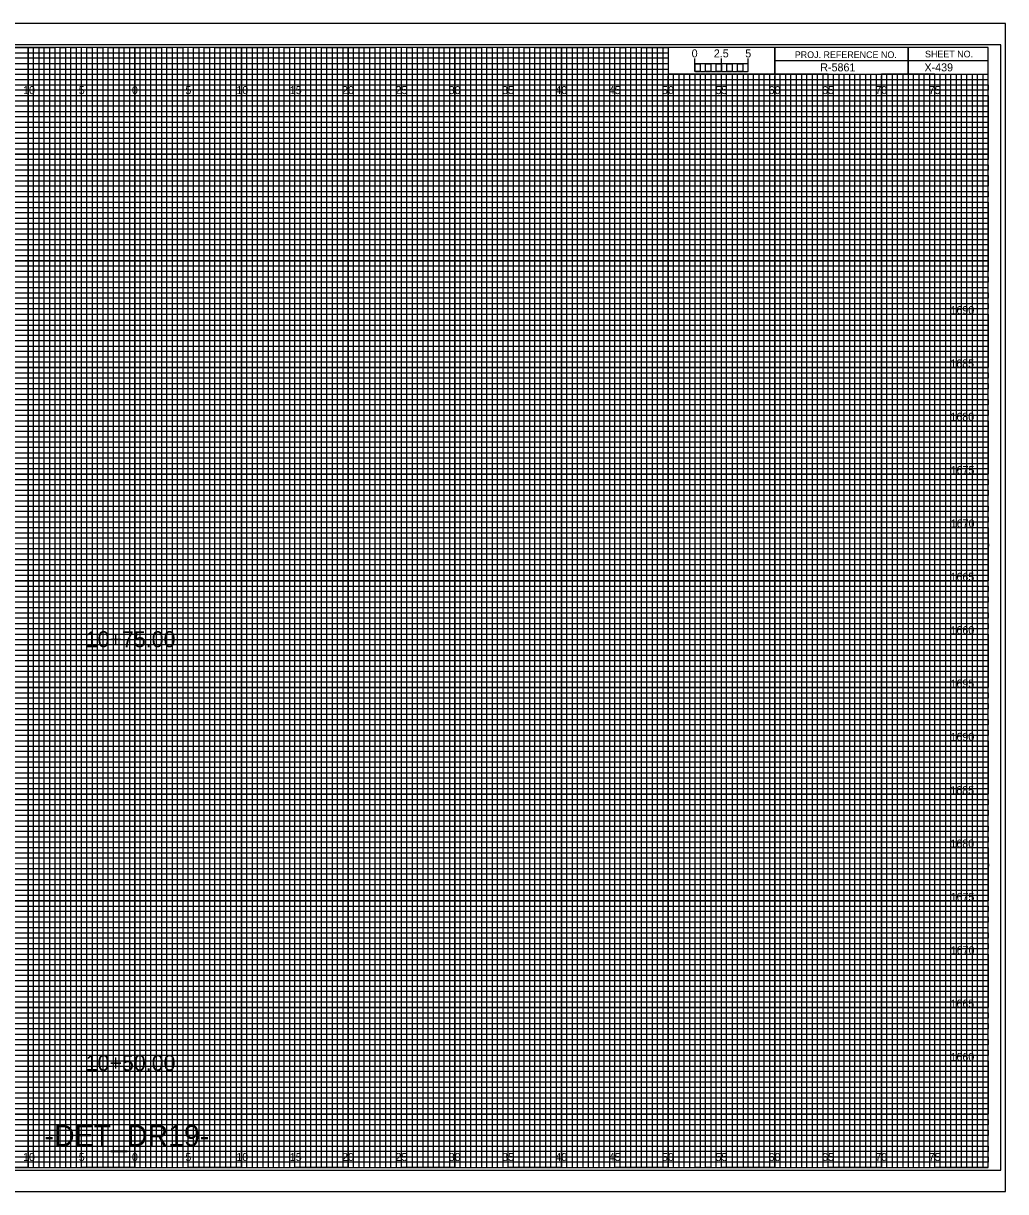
# Model space of a CAD drawing. Extents: x -7 to 162, y -2 to 327.
# Drawn here: x 69.5 to 161.7, y 107.7 to 217.2 of the extents above; entities that cross this region are included whole.
import ezdxf

# ---------------------------------------------------------------- set-up
doc = ezdxf.new("R2010")
doc.units = 0
for name, color, linetype in [('Prop Horizontal Alignment', 7, 'Continuous'), ('Prop XS Alignment Label', 7, 'Continuous'), ('Prop XS Bar Scale Labels', 7, 'Continuous'), ('Prop XS Project Number', 7, 'Continuous'), ('Prop XS Sheet Number', 7, 'Continuous'), ('Raster_Level_0', 7, 'Continuous'), ('Scratch_Level_3', 7, 'Continuous'), ('Sheet Cross Section CELL', 7, 'Continuous'), ('Sheet Cross Section Grid Major CELL', 7, 'Continuous'), ('Sheet Cross Section Grid Middle CELL', 7, 'Continuous'), ('Sheet Cross Section Grid Minor 1 CELL', 7, 'Continuous'), ('Sheet Cross Section Grid Minor 2 CELL', 7, 'Continuous'), ('Sheet Cross Section Scale CELL', 7, 'Continuous'), ('Sheet Cutting Line CELL', 7, 'Continuous'), ('Sheet DOT Grid CELL', 7, 'Continuous'), ('Sheet Plot Border Inside CELL', 7, 'Continuous'), ('Sheet Plot Border Outside CELL', 7, 'Continuous')]:
    doc.layers.add(name, color=color, linetype=linetype)

msp = doc.modelspace()

# ---------------------------------------------------------------- linework, layer by layer
at = {"layer": 'Sheet Cross Section CELL'}
for p, q in [((152.5, 215), (152.5, 212.5)), ((152.5, 212.5), (152.5, 215)), ((160, 213.75), (140, 213.75)), ((140, 213.75), (140, 212.5)), ((140, 212.5), (160, 212.5))]:
    msp.add_line(p, q, dxfattribs=at)
for points in [[(160, 215), (0, 215), (0, 110), (160, 110)], [(140, 215), (130, 215), (130, 212.52), (140, 212.52)], [(160, 215), (140, 215), (140, 212.5), (160, 212.5)]]:
    msp.add_lwpolyline(points, close=True, dxfattribs=at)
at = {"layer": 'Sheet Cross Section Grid Major CELL'}
for p, q in [((75, 215), (70, 215)), ((70, 215), (70, 110)), ((75, 110), (75, 215)), ((85, 215), (80, 215)), ((80, 215), (80, 110)), ((85, 110), (85, 215)), ((95, 215), (90, 215)), ((90, 215), (90, 110)), ((95, 110), (95, 215)), ((105, 215), (100, 215)), ((100, 215), (100, 110)), ((105, 110), (105, 215)), ((115, 215), (110, 215)), ((110, 215), (110, 110)), ((115, 110), (115, 215)), ((125, 215), (120, 215)), ((120, 215), (120, 110)), ((125, 110), (125, 215)), ((130, 215), (130, 110)), ((135, 110), (135, 212.5)), ((145, 212.5), (140, 212.5)), ((140, 212.5), (140, 110)), ((145, 110), (145, 212.5)), ((155, 212.5), (150, 212.5)), ((150, 212.5), (150, 110)), ((155, 110), (155, 212.5)), ((70, 110), (65, 110)), ((80, 110), (75, 110)), ((90, 110), (85, 110)), ((100, 110), (95, 110)), ((110, 110), (105, 110)), ((120, 110), (115, 110)), ((130, 110), (125, 110)), ((140, 110), (135, 110)), ((150, 110), (145, 110)), ((160, 110), (155, 110)), ((160, 110), (160, 110))]:
    msp.add_line(p, q, dxfattribs=at)
for points in [[(0, 210), (160, 210), (160, 205), (0, 205)], [(0, 200), (160, 200), (160, 195), (0, 195)], [(0, 190), (160, 190), (160, 185), (0, 185)], [(0, 180), (160, 180), (160, 175), (0, 175)], [(0, 170), (160, 170), (160, 165), (0, 165)], [(0, 160), (160, 160), (160, 155), (0, 155)], [(0, 150), (160, 150), (160, 145), (0, 145)], [(0, 140), (160, 140), (160, 135), (0, 135)], [(0, 130), (160, 130), (160, 125), (0, 125)], [(0, 120), (160, 120), (160, 115), (0, 115)]]:
    msp.add_lwpolyline(points, dxfattribs=at)
at = {"layer": 'Sheet Cross Section Grid Middle CELL'}
for points in [[(67.5, 215), (72.5, 215), (72.5, 110), (77.5, 110), (77.5, 215), (82.5, 215), (82.5, 110), (87.5, 110), (87.5, 215), (92.5, 215), (92.5, 110), (97.5, 110), (97.5, 215), (102.5, 215), (102.5, 110), (107.5, 110), (107.5, 215), (112.5, 215), (112.5, 110), (117.5, 110), (117.5, 215), (122.5, 215), (122.5, 110), (127.5, 110), (127.5, 215), (129.97, 215), (130, 215), (130, 212.5), (132.5, 212.5), (132.5, 110), (137.5, 110), (137.5, 212.5), (142.5, 212.5), (142.5, 110), (147.5, 110), (147.5, 212.5), (152.5, 212.5), (152.5, 110), (157.5, 110), (157.5, 212.5)], [(0, 212.5), (137.5, 212.5)], [(0, 202.5), (160, 202.5), (160, 207.5), (0, 207.5)], [(0, 192.5), (160, 192.5), (160, 197.5), (0, 197.5)], [(0, 182.5), (160, 182.5), (160, 187.5), (0, 187.5)], [(0, 172.5), (160, 172.5), (160, 177.5), (0, 177.5)], [(0, 162.5), (160, 162.5), (160, 167.5), (0, 167.5)], [(0, 152.5), (160, 152.5), (160, 157.5), (0, 157.5)], [(0, 142.5), (160, 142.5), (160, 147.5), (0, 147.5)], [(0, 132.5), (160, 132.5), (160, 137.5), (0, 137.5)], [(0, 122.5), (160, 122.5), (160, 127.5), (0, 127.5)], [(0, 112.5), (160, 112.5), (160, 117.5), (0, 117.5)]]:
    msp.add_lwpolyline(points, dxfattribs=at)
at = {"layer": 'Sheet Cross Section Grid Minor 1 CELL'}
for p, q in [((0, 214.5), (130, 214.5)), ((130, 213.99), (0, 213.99)), ((130, 214.5), (130, 213.99)), ((0, 213.5), (130, 213.5)), ((130, 212.94), (0, 212.94)), ((130, 213.5), (130, 212.94)), ((0, 212), (160, 212))]:
    msp.add_line(p, q, dxfattribs=at)
for points in [[(0, 211.5), (135, 211.5), (160, 211.5), (160, 211), (0, 211)], [(0, 210.5), (160, 210.5), (160, 209.5), (0, 209.5)], [(0, 209), (160, 209), (160, 208.5), (0, 208.49)], [(0, 208), (160, 208), (160, 207), (0, 207)], [(0, 206.5), (160, 206.5), (160, 206), (0, 206)], [(0, 205.5), (160, 205.5), (160, 204.5), (0, 204.5)], [(0, 204), (160, 204), (160, 203.5), (0, 203.5)], [(0, 203), (160, 203), (160, 202), (0, 202)], [(0, 201.5), (160, 201.5), (160, 201), (0, 201)], [(0, 200.5), (160, 200.5), (160, 199.5), (0, 199.5)], [(0, 199), (160, 199), (160, 198.5), (0, 198.5)], [(0, 198), (160, 198), (160, 196.97), (160, 196.5), (160, 196), (0, 196)], [(0, 197), (160, 197), (160, 196.5), (0, 196.5)], [(0, 195.5), (160, 195.5), (160, 194.5), (0, 194.52)], [(0, 194.52), (160, 194.5), (160, 194), (0, 194)], [(0, 193.5), (160, 193.5), (160, 193), (0, 193)], [(0, 192), (160, 192), (160, 191.5), (0, 191.5)], [(0, 191), (160, 191), (160, 190.5), (0, 190.5)], [(-0.04, 189.44), (160, 189.44), (160, 188.94), (-0.04, 188.94)], [(0, 188.5), (160, 188.5), (160, 188), (0, 188)], [(0, 187), (160, 187), (160, 186.5), (0, 186.5)], [(0, 186), (160, 186), (160, 185.5), (0, 185.5)], [(0, 184.5), (160, 184.5), (160, 184), (0, 184)], [(0, 183.5), (160, 183.5), (160, 183), (0, 183)], [(0, 182), (160, 182), (160, 181.5), (0, 181.5)], [(0, 181), (160, 181), (160, 180.5), (0, 180.5)], [(0, 179.5), (160, 179.5), (160, 178.99), (0, 179)], [(0, 178.5), (160, 178.5), (160, 178), (0, 178)], [(0, 177), (160, 177), (160, 176.5), (0, 176.5)], [(0, 176), (160, 176), (160, 175.5), (0, 175.5)], [(0, 174.5), (160, 174.5), (160, 174), (0, 174)], [(0, 173.5), (160, 173.5), (160, 173), (0, 173)], [(0, 172), (160, 172), (160, 171.5), (0, 171.5)], [(0, 171), (160, 171), (160, 170.5), (0, 170.5)], [(0, 169.5), (160, 169.5), (160, 169), (0, 169)], [(0, 168.5), (160.03, 168.46), (160, 168), (0, 168)], [(0, 167), (160, 167), (160, 166.5), (0, 166.5)], [(0, 166), (160, 166), (160, 165.5), (0, 165.5)], [(0, 164.5), (160, 164.5), (160, 164), (0, 164)], [(0, 163.5), (160, 163.5), (160, 163), (0, 163)], [(0, 162), (160, 162), (160, 161.5), (0, 161.5)], [(0, 161), (160, 161), (160, 160.5), (0, 160.5)], [(0, 159.5), (160, 159.5), (160, 159), (0, 159)], [(0, 158.5), (160, 158.5), (160, 158), (0, 158)], [(0, 157), (160, 157), (160, 156.5), (0, 156.5)], [(0, 156), (160, 156), (160, 155.5), (0, 155.5)], [(0, 154.5), (160, 154.5), (160, 154), (0, 154)], [(0, 153.5), (160, 153.5), (160, 153), (0, 153)], [(0, 152), (160, 152), (160, 151.5), (0, 151.5)], [(0, 151), (160, 151), (160, 150.5), (0, 150.5)], [(0, 149.5), (160, 149.5), (160, 148.99), (0, 149)], [(0, 148.5), (160, 148.5), (160, 148), (0, 148)], [(0, 147), (160, 147), (160, 146.5), (0, 146.5)], [(0, 146), (160, 146), (160, 145.5), (0, 145.5)], [(0, 144.5), (160, 144.5), (160, 144), (0, 144)], [(0, 143.5), (160, 143.5), (160, 143), (0, 143)], [(0, 142), (160, 142), (160, 141.5), (0, 141.5)], [(0, 141), (160, 141), (160, 140.5), (0, 140.5)], [(0, 139.5), (160, 139.5), (160, 139), (0, 139)], [(0, 138.5), (160.03, 138.46), (160, 138), (0, 138)], [(0, 137), (160, 137), (160, 136.5), (0, 136.5)], [(0, 136), (160, 136), (160, 135.5), (0, 135.5)], [(0, 134.5), (160, 134.5), (160, 134), (0, 134)], [(0, 133.5), (160, 133.5), (160, 133), (0, 133)], [(0, 132), (160, 132), (160, 131.5), (0, 131.5)], [(0, 131), (160, 131), (160, 130.5), (0, 130.5)], [(0, 129.5), (160, 129.5), (160, 129), (0, 129)], [(0, 128.5), (160, 128.5), (160, 128), (0, 128)], [(0, 127), (160, 127), (160, 126.5), (0, 126.5)], [(0, 126), (160, 126), (160, 125.5), (0, 125.5)], [(0, 124.5), (160, 124.5), (160, 124), (0, 124)], [(0, 123.5), (160, 123.5), (160, 123), (0, 123)], [(0, 122), (160, 122), (160, 121.5), (0, 121.5)], [(0, 121), (160, 121), (160, 120.5), (0, 120.5)], [(0, 119.5), (160, 119.5), (160, 119), (0, 119)], [(0, 118.5), (160, 118.5), (160, 118), (0, 118)], [(0, 117), (160, 117), (160, 116.5), (0, 116.5)], [(0, 116), (160, 116), (160, 115.5), (0, 115.5)], [(0, 114.5), (160, 114.5), (160, 114), (0, 114)], [(0, 113.5), (160, 113.5), (160, 113), (0, 113)], [(0, 112), (160, 112), (160, 111.5), (0, 111.5)], [(0, 111), (160, 111), (160, 110.5), (0, 110.5)]]:
    msp.add_lwpolyline(points, dxfattribs=at)
at = {"layer": 'Sheet Cross Section Grid Minor 2 CELL'}
for p, q in [((133.5, 212.5), (133, 212.5)), ((133, 212.5), (133, 110)), ((133.5, 110), (133.5, 212.5)), ((134.5, 212.5), (134, 212.5)), ((134, 212.5), (134, 110)), ((134.5, 110), (134.5, 212.5)), ((133, 110), (132.5, 110)), ((134, 110), (133.5, 110))]:
    msp.add_line(p, q, dxfattribs=at)
for points in [[(70, 110), (70.5, 110), (70.5, 215), (71, 215), (71, 110)], [(71, 110), (71.5, 110), (71.5, 215), (72, 215), (72, 110)], [(72.5, 110), (73, 110), (73, 215), (73.5, 215), (73.5, 110)], [(73.5, 110), (74, 110), (74, 215), (74.5, 215), (74.5, 110)], [(75, 110), (75.5, 110), (75.5, 215), (76, 215), (76, 110)], [(76, 110), (76.5, 110), (76.5, 215), (77, 215), (77, 110)], [(77.5, 110), (78, 110), (78, 215), (78.5, 215), (78.5, 110)], [(78.5, 110), (79, 110), (79, 215), (79.5, 215), (79.5, 110)], [(80, 110), (80.5, 110), (80.5, 215), (81, 215), (81, 110)], [(81, 110), (81.5, 110), (81.5, 215), (82, 215), (82, 110)], [(82.5, 110), (83, 110), (83, 215), (83.5, 215), (83.5, 110)], [(83.5, 110), (84, 110), (84, 215), (84.5, 215), (84.5, 110)], [(85, 110), (85.5, 110), (85.5, 215), (86, 215), (86, 110)], [(86, 110), (86.5, 110), (86.5, 215), (87, 215), (87, 110)], [(87.5, 110), (88, 110), (88, 215), (88.5, 215), (88.5, 110)], [(88.5, 110), (89, 110), (89, 215), (89.5, 215), (89.5, 110)], [(90, 110), (90.5, 110), (90.5, 215), (91, 215), (91, 110)], [(91, 110), (91.5, 110), (91.5, 215), (92, 215), (92, 110)], [(92.5, 110), (93, 110), (93, 215), (93.5, 215), (93.5, 110)], [(93.5, 110), (94, 110), (94, 215), (94.5, 215), (94.5, 110)], [(95, 110), (95.5, 110), (95.5, 215), (96, 215), (96, 110)], [(96, 110), (96.5, 110), (96.5, 215), (97, 215), (97, 110)], [(97.5, 110), (98, 110), (98, 215), (98.5, 215), (98.5, 110)], [(98.5, 110), (99, 110), (99, 215), (99.5, 215), (99.5, 110)], [(100, 110), (100.5, 110), (100.5, 215), (101, 215), (101, 110)], [(101, 110), (101.5, 110), (101.5, 215), (102, 215), (102, 110)], [(102.5, 110), (103, 110), (103, 215), (103.5, 215), (103.5, 110)], [(103.5, 110), (104, 110), (104, 215), (104.5, 215), (104.5, 110)], [(105, 110), (105.5, 110), (105.5, 215), (106, 215), (106, 110)], [(106, 110), (106.5, 110), (106.5, 215), (107, 215), (107, 110)], [(107.5, 110), (108, 110), (108, 215), (108.5, 215), (108.5, 110)], [(108.5, 110), (109, 110), (109, 215), (109.5, 215), (109.5, 110)], [(110, 110), (110.5, 110), (110.5, 215), (111, 215), (111, 110)], [(111, 110), (111.5, 110), (111.5, 215), (112, 215), (112, 110)], [(112.5, 110), (113, 110), (113, 215), (113.5, 215), (113.5, 110)], [(113.5, 110), (114, 110), (114, 215), (114.5, 215), (114.5, 110)], [(115, 110), (115.5, 110), (115.5, 215), (116, 215), (116, 110)], [(116, 110), (116.5, 110), (116.5, 215), (117, 215), (117, 110)], [(117.5, 110), (118, 110), (118, 215), (118.5, 215), (118.5, 110)], [(118.5, 110), (119, 110), (119, 215), (119.5, 215), (119.5, 110)], [(120, 110), (120.5, 110), (120.5, 215), (121, 215), (121, 110)], [(121, 110), (121.5, 110), (121.5, 215), (122, 215), (122, 110)], [(122.5, 110), (123, 110), (123, 215), (123.5, 215), (123.5, 110)], [(123.5, 110), (124, 110), (124, 215), (124.5, 215), (124.5, 110)], [(125, 110), (125.5, 110), (125.5, 215), (126, 215), (126, 110)], [(126, 110), (126.5, 110), (126.5, 215), (127, 215), (127, 110)], [(127.5, 110), (128, 110), (128, 215), (128.5, 215), (128.5, 110)], [(128.5, 110), (129, 110), (129, 215), (129.5, 215), (129.5, 110)], [(130, 110), (130.5, 110), (130.5, 212.5), (131.01, 212.5), (131.01, 110)], [(131, 110), (131.5, 110), (131.5, 212.5), (132, 212.5), (132, 110)], [(135, 110), (135.49, 110), (135.49, 212.5), (136, 212.5), (136, 110)], [(136, 110), (136.5, 110), (136.5, 212.5), (137.03, 212.5), (137.03, 110)], [(137.5, 110), (138, 110), (138, 212.5), (138.5, 212.5), (138.5, 110)], [(138.5, 110), (139, 110), (139, 212.5), (139.5, 212.5), (139.5, 110)], [(140, 110), (140.5, 110), (140.5, 212.5), (141, 212.5), (141, 110)], [(141, 110), (141.5, 110), (141.5, 212.5), (142, 212.5), (142, 110)], [(142.5, 110), (143, 110), (143, 212.5), (143.5, 212.5), (143.5, 110)], [(143.5, 110), (144, 110), (144, 212.5), (144.5, 212.5), (144.5, 110)], [(145, 110), (145.5, 110), (145.5, 212.5), (146, 212.5), (146, 110)], [(146, 110), (146.5, 110), (146.5, 212.5), (147, 212.5), (147, 110)], [(147.5, 110), (148, 110), (148, 212.5), (148.5, 212.5), (148.5, 110)], [(148.5, 110), (149, 110), (149, 212.5), (149.5, 212.5), (149.5, 110)], [(150, 110), (150.5, 110), (150.5, 212.5), (151, 212.5), (151, 110)], [(151, 110), (151.5, 110), (151.5, 212.5), (152, 212.5), (152, 110)], [(152.5, 110), (153, 110), (153, 212.5), (153.5, 212.5), (153.5, 110)], [(153.5, 110), (154, 110), (154, 212.5), (154.5, 212.5), (154.5, 110)], [(155, 110), (155.5, 110), (155.5, 212.5), (156, 212.5), (156, 110)], [(156, 110), (156.5, 110), (156.5, 212.5), (157, 212.5), (157, 110)], [(157.5, 110), (158, 110), (158, 212.5), (158.5, 212.5), (158.5, 110)], [(158.5, 110), (159, 110), (159, 212.5), (159.5, 212.5), (159.5, 110)]]:
    msp.add_lwpolyline(points, dxfattribs=at)
at = {"layer": 'Sheet Cross Section Scale CELL'}
for p, q in [((132.5, 212.75), (132.5, 213.95)), ((132.5, 213.45), (132.5, 213.95)), ((135, 212.75), (135, 213.95)), ((137.5, 212.75), (137.5, 213.95)), ((137.5, 213.45), (137.5, 213.95))]:
    msp.add_line(p, q, dxfattribs=at)
for points in [[(137.5, 213.45), (132.5, 213.45), (132.5, 212.75), (137.5, 212.75)], [(132.5, 213.45), (133, 213.45), (133, 212.75), (132.5, 212.75)], [(133.5, 213.45), (134, 213.45), (134, 212.75), (133.5, 212.75)], [(134.5, 213.45), (135, 213.45), (135, 212.75), (134.5, 212.75)], [(135.5, 213.45), (136, 213.45), (136, 212.75), (135.5, 212.75)], [(136.5, 213.45), (137, 213.45), (137, 212.75), (136.5, 212.75)]]:
    msp.add_lwpolyline(points, close=True, dxfattribs=at)
at = {"layer": 'Sheet Cutting Line CELL'}
for p, q in [((161.65, 217.25), (-6.7, 217.25)), ((-6.7, 107.75), (161.65, 107.75))]:
    msp.add_line(p, q, dxfattribs=at)
at = {"layer": 'Sheet DOT Grid CELL'}
for p, q in [((70, 110), (70, 215)), ((75, 110), (75, 215)), ((80, 110), (80, 215)), ((85, 110), (85, 215)), ((90, 110), (90, 215)), ((95, 110), (95, 215)), ((100, 110), (100, 215)), ((105, 110), (105, 215)), ((110, 110), (110, 215)), ((115, 110), (115, 215)), ((120, 110), (120, 215)), ((125, 110), (125, 215)), ((130, 110), (130, 212.34)), ((135, 110), (135, 212.34)), ((140, 110), (140, 212.34)), ((145, 110), (145, 212.34)), ((150, 110), (150, 212.34)), ((155, 110), (155, 212.34)), ((0, 210), (160, 210)), ((0, 205), (160, 205)), ((0, 200), (160, 200)), ((0, 195), (160, 195)), ((0, 190), (160, 190)), ((0, 185), (160, 185)), ((0, 180), (160, 180)), ((0, 175), (160, 175)), ((0, 170), (160, 170)), ((0, 165), (160, 165)), ((0, 160), (160, 160)), ((0, 155), (160, 155)), ((0, 150), (160, 150)), ((0, 145), (160, 145)), ((0, 140), (160, 140)), ((0, 135), (160, 135)), ((0, 130), (160, 130)), ((0, 125), (160, 125)), ((0, 120), (160, 120)), ((0, 115), (160, 115))]:
    msp.add_line(p, q, dxfattribs=at)
at = {"layer": 'Sheet Plot Border Inside CELL'}
msp.add_lwpolyline([(-5.4, 109.75), (161.2, 109.75), (161.2, 215.25), (-5.4, 215.25)], close=True, dxfattribs=at)
at = {"layer": 'Sheet Plot Border Outside CELL'}
msp.add_lwpolyline([(-6.7, 107.75), (161.65, 107.75), (161.65, 217.25), (-6.7, 217.25)], close=True, dxfattribs=at)

# ---------------------------------------------------------------- texts
at = {"layer": 'Prop Horizontal Alignment'}
for s, p in [('10+75.00', (75.39, 158.78)), ('10+50.00', (75.39, 119.07))]:
    msp.add_text(s, height=1.5, dxfattribs=at).set_placement(p)
at = {"layer": 'Prop XS Alignment Label'}
msp.add_text('-DET_DR19-', height=2, dxfattribs=at).set_placement((71.53, 112))
at = {"layer": 'Prop XS Bar Scale Labels'}
for s, p in [('2.5', (134.29, 214.06)), ('5', (137.24, 214.06))]:
    msp.add_text(s, height=0.75, dxfattribs=at).set_placement(p)
at = {"layer": 'Prop XS Project Number'}
msp.add_text('R-5861', height=0.75, dxfattribs=at).set_placement((144.27, 212.75))
at = {"layer": 'Prop XS Sheet Number'}
msp.add_text('X-439', height=0.75, dxfattribs=at).set_placement((154.04, 212.75))
at = {"layer": 'Raster_Level_0'}
for s, p in [('10', (69.52, 210.62)), ('5', (74.74, 210.62)), ('0', (79.73, 210.62)), ('0', (79.73, 210.62)), ('5', (84.74, 210.62)), ('10', (89.52, 210.62)), ('15', (94.53, 210.62)), ('20', (99.43, 210.62)), ('25', (104.44, 210.62)), ('30', (109.43, 210.62)), ('35', (114.44, 210.62)), ('40', (119.43, 210.62)), ('45', (124.44, 210.62)), ('50', (129.43, 210.62)), ('55', (134.44, 210.62)), ('60', (139.43, 210.62)), ('65', (144.44, 210.62)), ('70', (149.43, 210.62)), ('75', (154.44, 210.62)), ('10', (69.52, 110.62)), ('5', (74.74, 110.62)), ('0', (79.73, 110.62)), ('0', (79.73, 110.62)), ('5', (84.74, 110.62)), ('10', (89.52, 110.62)), ('15', (94.53, 110.62)), ('20', (99.43, 110.62)), ('25', (104.44, 110.62)), ('30', (109.43, 110.62)), ('35', (114.44, 110.62)), ('40', (119.43, 110.62)), ('45', (124.44, 110.62)), ('50', (129.43, 110.62)), ('55', (134.44, 110.62)), ('60', (139.43, 110.62)), ('65', (144.44, 110.62)), ('70', (149.43, 110.62)), ('75', (154.44, 110.62))]:
    msp.add_text(s, height=0.75, dxfattribs=at).set_placement(p)
at = {"layer": 'Scratch_Level_3'}
for s, p in [('1690', (156.48, 190)), ('1685', (156.46, 185)), ('1680', (156.47, 180)), ('1675', (156.49, 175)), ('1670', (156.5, 170)), ('1665', (156.48, 165)), ('1660', (156.48, 160)), ('1695', (156.48, 155)), ('1690', (156.48, 150)), ('1685', (156.46, 145)), ('1680', (156.47, 140)), ('1675', (156.49, 135)), ('1670', (156.5, 130)), ('1665', (156.48, 125)), ('1660', (156.48, 120))]:
    msp.add_text(s, height=0.75, dxfattribs=at).set_placement(p)
at = {"layer": 'Sheet Cross Section CELL'}
for s, p in [('PROJ. REFERENCE NO.', (141.88, 214)), ('SHEET NO.', (154.09, 214.06))]:
    msp.add_text(s, height=0.625, dxfattribs=at).set_placement(p)
at = {"layer": 'Sheet Cross Section Scale CELL'}
msp.add_text('0', height=0.75, dxfattribs=at).set_placement((132.21, 214.06))

doc.saveas('drawing.dxf')
